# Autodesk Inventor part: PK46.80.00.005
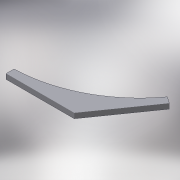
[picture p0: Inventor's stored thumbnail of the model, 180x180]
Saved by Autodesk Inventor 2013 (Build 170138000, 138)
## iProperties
Shininess: 64.0
Length Units: 11269
Angle Units: 11279
Time Units: 11290
Mass Units: 11283
Length Display Precision: 3
Angle Display Precision: 2
Compacted: True
Part Number: PK46.80.00.005
Document SubType Name: Modeling
Created: 2005-01
Material: Steel, Mild
Designer: SAlex
Manufacturer: Standard
Standards Organization: Custom
Density: 7.86 g/cm^3
Mass: 2156.78 g
Surface Area: 479.373 cm^2
Volume: 274.4 cm^3
Density: 0.0
Volumn: 0.0
Area: 0.0
PropertySet Name: Model Information
Control State: 0
Master: False
Checked Out: False
Checked Out Date: 2008-10-15
Last Check In Date: 2008-10-15
Author: SAlex
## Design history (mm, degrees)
sketch "Sketch1"
  geometry: L1 (0, 0)-(0, -25); L2 (0, -25)-(215.342, -25); L3 (215.342, -25)-(338.857, 151.398); L4 (338.857, 151.398)-(318.378, 165.737); L5 (-10, -36.05)-(-10, 407.877); L6 (-10, 407.877)-(215.342, -25); L7 (-10, 407.877)-(372.226, 140.24); A1 r 408 centre (-10, 407.877) between (0, 0) and (318.378, 165.737)
  constraints: 14 end point, 3 perpendicular, 2 point on circle, 1 centre point, 1 parallel, 1 vertical, 1 other
  dimensions: "d0" = 408 radius of A1; "d1" = 25 distance of L1.start L1.end; "d9" = 10 distance between parallel lines of L1 L5; "d10" = 10 distance between parallel lines of L4 L7; "d11" = 55 deg angle of L7 L5; "d12" = 27.5 deg angle of L7 L6 (= 0.5 x d11)
extrude "Extrusion1" new body sketch "Sketch1" distance "d7" = 16; taper "d8" = 0 deg
body "Solid1"
